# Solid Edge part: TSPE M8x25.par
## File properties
Subject: Vite TSPEI M8x25
Author: g_deluca
Template: RBuno.par
Last saved by: g_deluca
Revision: 24
Application: Solid Edge
Company: EFFEBI S.p.A.
Codice: Codice
Indice rev.: Rev.
Data rev.: Data rev.
Firma rev.: Firma rev.
Descrizione rev.: Descrizione rev.
Densità: 7860.000 kg/m^3
Precisione: 0.99
Tipo di contenuto documento: 0
Document Number: UNI 5933
Material: Classe 10.9
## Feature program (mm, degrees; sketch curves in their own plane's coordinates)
sketch for "unnamed RevolvedProtrusion 1" plane through (0, 0, 0) normal (0, -1, 0) x-axis (1, 0, 0)
revolve "unnamed RevolvedProtrusion 1" add full turn 360 deg
sketch for "unnamed Protrusion 1" plane through (0, 0, 4.3) normal (0, 0, 1) x-axis (1, 0, 0)
  circle centre (0, 0) radius 4
extrude "unnamed Protrusion 1" add finite 25 along -normal
sketch for "ExtrudedCutout_1" plane through (0, 0, 4.3) normal (0, 0, 1) x-axis (1, 0, 0)
  line (-2.5, 1.1547) -> (-2.5, -1.7321)
  line (0, -3.1754) -> (-2.5, -1.7321)
  line (0, -3.1754) -> (2.5, -1.7321)
  line (2.5, 1.1547) -> (2.5, -1.7321)
  line (2.5, 1.1547) -> (0, 2.5981)
  line (-2.5, 1.1547) -> (0, 2.5981)
extrude "ExtrudedCutout_1" cut finite 3.5 along -normal
thread "unnamed Thread 1"
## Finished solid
Body 1: solid body, 12 faces, 22 edges, 12 vertices.
  Faces by surface: plane 9, cylinder 2, cone 1
  Edges by curve: line 18, circle 4
Bounding box of the edges (mm): 15.600 x 15.600 x 25.000, from (-7.8, -7.8, -20.7) to (7.8, 7.8, 4.3).
Cylindrical faces by radius (mm): R4 x1, R7.8 x1
Conical faces (half-angle, radius in mm at the cone's reference point): 45 deg R4 x1
Planar faces by outward normal: +x 1, +z 2, -x 1, -z 1, oblique 4
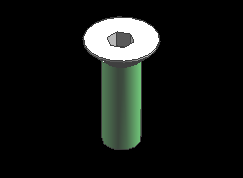
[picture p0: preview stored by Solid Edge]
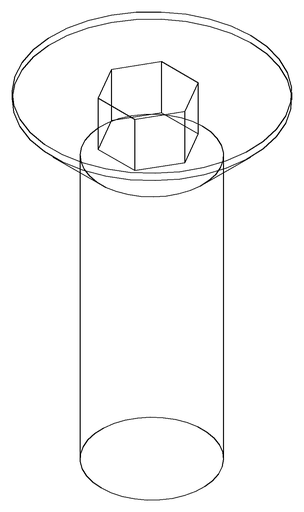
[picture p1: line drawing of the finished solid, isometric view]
